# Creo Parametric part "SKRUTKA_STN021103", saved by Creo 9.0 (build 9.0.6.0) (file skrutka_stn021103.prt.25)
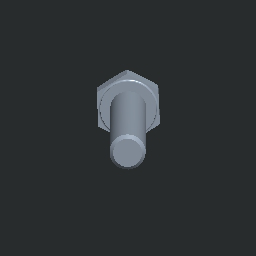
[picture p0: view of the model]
Units: Custom; MM, KILOGRAM, SECS
Materials in the file: OCEL_N

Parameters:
  WERKSTOFF = "8.8"
  KATEGORIE = "4"
  NAZOV = "SKRUTKA_STN021103"
  NORMA = "STN 02 1103"
  N1 = "021"
  N2 = "21"
  N3 = "1"
  PTC_MATERIAL_NAME = "OCEL_N"
  PLACEMENT = "A"

Other parameters: HMOTNOST, HUSTOTA, HMOTNOST_1, D50, D2, D7, D25, D30, THREADS_PER_INCH

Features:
  1. chamfer
  2. datum plane "DTM1"
  3. protrusion
  4. datum plane "DTM6"
  5. cut
  6. datum plane "DTM7"
  7. cut
  8. datum plane "DTM8"
  9. datum plane "DTM9"

Layers: BEZUGSEBENEN, KONSTRUKTIONSELEMENTE, NORMTEILE

Family table entries: SKRUTKA_M3X4, SKRUTKA_STN021103, value(d_val), value(i_val), SKRUTKA_M3X5, SKRUTKA_STN021103, SKRUTKA_M3X6, SKRUTKA_STN021103, SKRUTKA_M3X8, SKRUTKA_STN021103, 2/ , SKRUTKA_M3X10, SKRUTKA_STN021103, 2/$, SKRUTKA_M3X12, SKRUTKA_STN021103, 2/(, SKRUTKA_M3X16, SKRUTKA_STN021103, 2/0, SKRUTKA_M3X20, SKRUTKA_STN021103, 2/4, SKRUTKA_M3X25, SKRUTKA_STN021103, 2/9, SKRUTKA_M3X30, SKRUTKA_STN021103, 2/>, SKRUTKA_M4X8, SKRUTKA_STN021103, 2/ , SKRUTKA_M4X10, SKRUTKA_STN021103, 2/$, SKRUTKA_M4X12, SKRUTKA_STN021103, 2/(, SKRUTKA_M4X16, SKRUTKA_STN021103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

Surfaces: 10 plane, 4 cone, 3 cylinder, 2 torus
